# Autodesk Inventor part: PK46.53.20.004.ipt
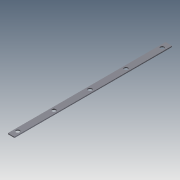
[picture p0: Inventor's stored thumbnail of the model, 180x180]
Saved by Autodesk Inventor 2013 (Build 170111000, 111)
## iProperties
Created: 2005-03
Part Number: PK46.53.20.004.ipt
Material: Steel, Mild
Document SubType Name: Modeling
Designer: HKostja
Manufacturer: Standard
Standards Organization: Custom
Density: 7.86 g/cm^3
Mass: 213.034 g
Surface Area: 216.345 cm^2
Volume: 27.1035 cm^3
Author: HKostja
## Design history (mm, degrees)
sketch "Эскиз1"
  geometry: L1 (0, 0)-(-20, 0); L2 (-20, 0)-(-20, 480); L3 (-20, 480)-(0, 480); L4 (0, 480)-(0, 0); L5 (-10, 480)-(-10, 0); C1 r 6 at (-10, 20); C2 r 6 at (-10, 130); C3 r 6 at (-10, 240); C4 r 6 at (-10, 350); C5 r 6 at (-10, 460)
  constraints: 10 end point, 5 centre point, 4 equal radius, 4 point on line, 3 midpoint, 2 parallel, 1 horizontal, 1 perpendicular, 1 other
  dimensions: "d0" = 20 distance of L1.start L1.end; "d1" = 480 distance of L3.end L1.start; "d2" = 110 distance of C2.centre C1.centre; "d3" = 110 distance of C3.centre C2.centre (= d2); "d4" = 110 distance of C5.centre C4.centre (= d2); "d5" = 110 distance of C4.centre C3.centre (= d2); "d6" = 20 distance from line of L1 C1.centre; "d7" = 12 diameter of C1
extrude "Выдавливание1" new body sketch "Эскиз1" distance "d8" = 3; taper "d9" = 0 deg
body "Solid1"
